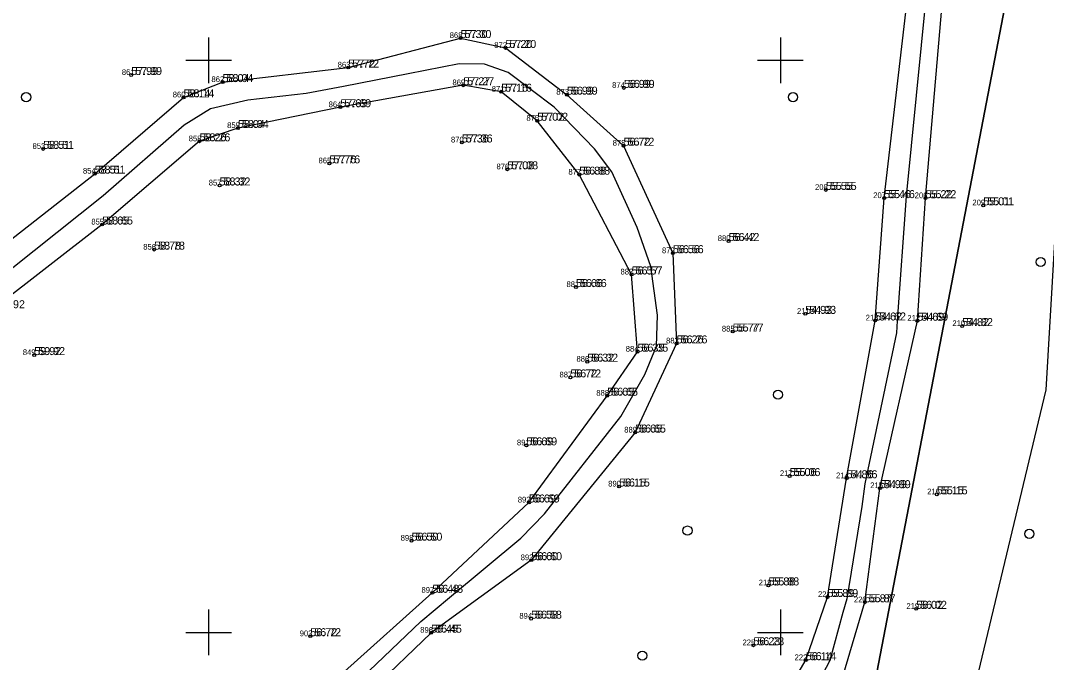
# Model space of a CAD drawing. Extents: x 554846 to 556995, y 6445875 to 6446723.
# Drawn here: x 555383.6 to 555473.3, y 6446097.4 to 6446153.5 of the extents above; entities that cross this region are included whole.
import ezdxf

# ---------------------------------------------------------------- set-up
doc = ezdxf.new("R2010")
doc.units = 0
for name, color, linetype in [('HALJASTUS', 7, 'Continuous'), ('KORGUS-EH2000', 7, 'Continuous'), ('MOOTKORG-EH2000', 7, 'Continuous'), ('MOOTMPUNKT', 7, 'Continuous'), ('MOOTNR', 7, 'Continuous'), ('MOOTPIIR', 7, 'Continuous'), ('PIIR', 7, 'Continuous'), ('TEE', 7, 'Continuous'), ('VORK', 7, 'Continuous')]:
    doc.layers.add(name, color=color, linetype=linetype)

msp = doc.modelspace()

# ---------------------------------------------------------------- linework, layer by layer
at = {"layer": 'HALJASTUS'}
for centre in [(555384.049, 6446146.781), (555451.109, 6446146.781), (555472.76, 6446132.363), (555449.791, 6446120.771), (555441.879, 6446108.897), (555471.771, 6446108.615), (555437.923, 6446097.966)]:
    msp.add_circle(centre, 0.4, dxfattribs=at)
at = {"layer": 'KORGUS-EH2000'}
for centre in [(555422.033, 6446151.944), (555425.956, 6446151.079), (555412.213, 6446149.366), (555393.235, 6446148.715), (555401.222, 6446148.095), (555422.273, 6446147.818), (555436.31, 6446147.587), (555397.814, 6446146.759), (555425.583, 6446147.254), (555431.331, 6446146.995), (555411.521, 6446145.9), (555402.569, 6446144.081), (555428.739, 6446144.714), (555385.532, 6446142.255), (555399.209, 6446142.919), (555422.143, 6446142.817), (555436.284, 6446142.533), (555410.559, 6446140.992), (555426.122, 6446140.471), (555390.037, 6446140.091), (555432.413, 6446140.005), (555400.96, 6446139.057), (555453.976, 6446138.669), (555459.068, 6446137.953), (555462.692, 6446137.947), (555467.738, 6446137.321), (555390.695, 6446135.647), (555445.472, 6446134.202), (555395.237, 6446133.451), (555440.596, 6446133.14), (555436.993, 6446131.28), (555432.12, 6446130.179), (555452.177, 6446127.836), (555458.286, 6446127.259), (555461.978, 6446127.235), (555445.832, 6446126.292), (555465.891, 6446126.77), (555440.927, 6446125.255), (555384.754, 6446124.235), (555437.502, 6446124.533), (555433.115, 6446123.656), (555431.632, 6446122.282), (555434.853, 6446120.682), (555437.295, 6446117.463), (555427.784, 6446116.344), (555450.807, 6446113.66), (555455.792, 6446113.469), (555435.891, 6446112.746), (555458.705, 6446112.603), (555463.681, 6446112.063), (555428.011, 6446111.351), (555417.745, 6446108.013), (555428.215, 6446106.306), (555448.952, 6446104.102), (555419.563, 6446103.459), (555454.113, 6446103.09), (555457.379, 6446102.627), (555461.87, 6446102.056), (555428.198, 6446101.197), (555419.454, 6446099.97), (555408.89, 6446099.662), (555447.636, 6446098.872), (555452.214, 6446097.567)]:
    msp.add_circle(centre, 0.125, dxfattribs=at)
at = {"layer": 'MOOTMPUNKT'}
for centre in [(555422.033, 6446151.944), (555425.956, 6446151.079), (555412.213, 6446149.366), (555393.235, 6446148.715), (555401.222, 6446148.095), (555422.273, 6446147.818), (555436.31, 6446147.587), (555397.814, 6446146.759), (555425.583, 6446147.254), (555431.331, 6446146.995), (555411.521, 6446145.9), (555402.569, 6446144.081), (555428.739, 6446144.714), (555385.532, 6446142.255), (555399.209, 6446142.919), (555422.143, 6446142.817), (555436.284, 6446142.533), (555410.559, 6446140.992), (555426.122, 6446140.471), (555390.037, 6446140.091), (555432.413, 6446140.005), (555400.96, 6446139.057), (555453.976, 6446138.669), (555459.068, 6446137.953), (555462.692, 6446137.947), (555467.738, 6446137.321), (555390.695, 6446135.647), (555445.472, 6446134.202), (555395.237, 6446133.451), (555440.596, 6446133.14), (555436.993, 6446131.28), (555432.12, 6446130.179), (555452.177, 6446127.836), (555458.286, 6446127.259), (555461.978, 6446127.235), (555445.832, 6446126.292), (555465.891, 6446126.77), (555440.927, 6446125.255), (555384.754, 6446124.235), (555437.502, 6446124.533), (555433.115, 6446123.656), (555431.632, 6446122.282), (555434.853, 6446120.682), (555437.295, 6446117.463), (555427.784, 6446116.344), (555450.807, 6446113.66), (555455.792, 6446113.469), (555435.891, 6446112.746), (555458.705, 6446112.603), (555463.681, 6446112.063), (555428.011, 6446111.351), (555417.745, 6446108.013), (555428.215, 6446106.306), (555448.952, 6446104.102), (555419.563, 6446103.459), (555454.113, 6446103.09), (555457.379, 6446102.627), (555461.87, 6446102.056), (555428.198, 6446101.197), (555419.454, 6446099.97), (555408.89, 6446099.662), (555447.636, 6446098.872), (555452.214, 6446097.567)]:
    msp.add_circle(centre, 0.125, dxfattribs=at)
at = {"layer": 'MOOTPIIR'}
msp.add_lwpolyline([(555856.555, 6446356.048), (555752.836, 6446263.064), (555653.542, 6446239.265), (555594.535, 6446196.056), (555554.977, 6446185.172), (555476.191, 6446171.978), (555473.224, 6446121.184), (555464.983, 6446086.881), (555439.929, 6446060.824), (555399.382, 6446041.363), (555318.618, 6446036.416), (555233.239, 6446050.269)], dxfattribs=at)
at = {"layer": 'PIIR'}
msp.add_lwpolyline([(555848.15, 6446270.05), (555770.44, 6446257.1), (555601.76, 6446236.19), (555592.08, 6446205.8), (555590.17, 6446199.81), (555547.72, 6446198.88), (555471.93, 6446166.68), (555437.75, 6445988.89), (555430.84, 6445989.84), (555424.9, 6445990.66), (555394.94, 6445995.15), (555348.46, 6446002.11), (555303.97, 6446008.78), (555290.27, 6445950.91), (555289.66, 6445948.39), (555259.76, 6445985.47)], dxfattribs=at)
msp.add_lwpolyline([(555594.35, 6446199.31), (555580.72, 6446194.53), (555573.2, 6446192.45), (555562.73, 6446139.8), (555499.33, 6446154.09), (555491.55, 6446119.62), (555486.57, 6446097.52), (555481.82, 6446076.44), (555475.25, 6446047.27), (555464.73, 6446000.58), (555471.74, 6445999.08), (555467.38, 6445984.82), (555437.75, 6445988.89), (555471.93, 6446166.68), (555547.72, 6446198.88), (555590.17, 6446199.81)], close=True, dxfattribs=at)
at = {"layer": 'TEE'}
for points in [[(555455.467, 6446096.135), (555457.379, 6446102.627), (555458.705, 6446112.603), (555461.978, 6446127.235), (555462.692, 6446137.947), (555464.165, 6446155.222), (555464.888, 6446168.091), (555460.718, 6446178.087), (555458.182, 6446181.43), (555454.567, 6446187.282), (555447.334, 6446193.455), (555438.945, 6446198.778), (555431.081, 6446205.966), (555443.842, 6446207.197), (555455.762, 6446204.58), (555468.833, 6446198.189), (555475.066, 6446194.836)], [(555449.194, 6446092.47), (555452.214, 6446097.567), (555454.113, 6446103.09), (555455.792, 6446113.469), (555458.286, 6446127.259), (555459.068, 6446137.953), (555461.161, 6446155.974), (555461.088, 6446167.397), (555455.935, 6446177.178), (555454.036, 6446179.674), (555450.224, 6446185.653), (555445.278, 6446190.027), (555436.561, 6446196.434), (555428.776, 6446203.669), (555411.969, 6446206.659), (555401.236, 6446203.893), (555388.023, 6446199.971), (555376.051, 6446196.325)], [(555462.761, 6446155.758), (555461.011, 6446138.135), (555460.216, 6446127.225), (555460.14, 6446126.188), (555457.395, 6446112.968), (555457.12, 6446110.989), (555455.797, 6446102.941), (555455.466, 6446101.723), (555454.331, 6446097.543), (555453.685, 6446096.323)], [(555330.138, 6446095.193), (555336.092, 6446099.058), (555343.079, 6446106.38), (555345.217, 6446109.048), (555355.929, 6446113.292), (555363.874, 6446119.42), (555374.157, 6446127.256), (555379.516, 6446131.875), (555390.037, 6446140.091), (555397.814, 6446146.759), (555401.222, 6446148.095), (555412.213, 6446149.366), (555422.033, 6446151.944), (555425.956, 6446151.079), (555431.331, 6446146.995), (555436.284, 6446142.533), (555440.596, 6446133.14), (555440.927, 6446125.255), (555437.295, 6446117.463), (555428.215, 6446106.306), (555419.454, 6446099.97), (555414.313, 6446095.012)], [(555413.39, 6446096.014), (555418.564, 6446100.937), (555421.075, 6446103.036), (555427.3, 6446108.241), (555429.382, 6446110.355), (555436.044, 6446118.871), (555438.142, 6446122.527), (555439.155, 6446125.025), (555439.244, 6446127.719), (555438.673, 6446131.988), (555437.48, 6446135.391), (555435.273, 6446140.241), (555433.753, 6446142.269), (555430.226, 6446145.893), (555426.19, 6446148.941), (555424.112, 6446149.657), (555421.914, 6446149.692), (555417.455, 6446148.825), (555411.786, 6446147.723), (555408.518, 6446147.087), (555403.418, 6446146.508), (555400.167, 6446145.764), (555397.852, 6446144.336), (555390.782, 6446138.154), (555380.688, 6446130.154)], [(555411.889, 6446096.584), (555419.563, 6446103.459), (555428.011, 6446111.351), (555434.853, 6446120.682), (555437.502, 6446124.533), (555436.993, 6446131.28), (555432.413, 6446140.005), (555428.739, 6446144.714), (555425.583, 6446147.254), (555422.273, 6446147.818), (555411.521, 6446145.9), (555402.569, 6446144.081), (555399.209, 6446142.919), (555390.695, 6446135.647), (555381.245, 6446128.33), (555374.773, 6446123.196), (555366.199, 6446116.974), (555358.225, 6446110.676), (555348.051, 6446105.874), (555346.97, 6446105.409), (555344.88, 6446103.864), (555338.651, 6446097.801), (555331.388, 6446092.027)]]:
    msp.add_lwpolyline(points, dxfattribs=at)
at = {"layer": 'VORK'}
for p, q in [((555400, 6446152), (555400, 6446148)), ((555450, 6446152), (555450, 6446148)), ((555398, 6446150), (555402, 6446150)), ((555448, 6446150), (555452, 6446150)), ((555400, 6446102), (555400, 6446098)), ((555450, 6446102), (555450, 6446098)), ((555398, 6446100), (555402, 6446100)), ((555448, 6446100), (555452, 6446100))]:
    msp.add_line(p, q, dxfattribs=at)

# ---------------------------------------------------------------- texts
at = {"layer": 'KORGUS-EH2000'}
for s, p in [('57.30', (555422.383, 6446151.944)), ('57.20', (555426.306, 6446151.079)), ('57.99', (555393.585, 6446148.715)), ('57.72', (555412.563, 6446149.366)), ('58.04', (555401.572, 6446148.095)), ('57.27', (555422.623, 6446147.818)), ('57.16', (555425.933, 6446147.254)), ('56.99', (555431.681, 6446146.995)), ('56.99', (555436.66, 6446147.587)), ('58.14', (555398.164, 6446146.759)), ('57.69', (555411.871, 6446145.9)), ('57.02', (555429.089, 6446144.714)), ('58.04', (555402.919, 6446144.081)), ('58.26', (555399.559, 6446142.919)), ('57.36', (555422.493, 6446142.817)), ('56.72', (555436.634, 6446142.533)), ('58.51', (555385.882, 6446142.255)), ('57.76', (555410.909, 6446140.992)), ('58.51', (555390.387, 6446140.091)), ('57.08', (555426.472, 6446140.471)), ('56.88', (555432.763, 6446140.005)), ('58.32', (555401.31, 6446139.057)), ('55.55', (555454.326, 6446138.669)), ('55.46', (555459.418, 6446137.953)), ('55.22', (555463.042, 6446137.947)), ('55.01', (555468.088, 6446137.321)), ('58.65', (555391.045, 6446135.647)), ('58.78', (555395.587, 6446133.451)), ('56.42', (555445.822, 6446134.202)), ('56.56', (555440.946, 6446133.14)), ('56.57', (555437.343, 6446131.28)), ('56.66', (555432.47, 6446130.179)), ('59.92', (555381.595, 6446128.33)), ('54.93', (555452.527, 6446127.836)), ('54.62', (555458.636, 6446127.259)), ('54.69', (555462.328, 6446127.235)), ('55.77', (555446.182, 6446126.292)), ('54.82', (555466.241, 6446126.77)), ('56.35', (555437.852, 6446124.533)), ('56.26', (555441.277, 6446125.255)), ('59.92', (555385.104, 6446124.235)), ('56.32', (555433.465, 6446123.656)), ('56.72', (555431.982, 6446122.282)), ('56.65', (555435.203, 6446120.682)), ('56.65', (555437.645, 6446117.463)), ('56.69', (555428.134, 6446116.344)), ('55.06', (555451.157, 6446113.66)), ('54.86', (555456.142, 6446113.469)), ('56.15', (555436.241, 6446112.746)), ('54.99', (555459.055, 6446112.603)), ('55.15', (555464.031, 6446112.063)), ('56.69', (555428.361, 6446111.351)), ('56.50', (555418.095, 6446108.013)), ('56.60', (555428.565, 6446106.306)), ('55.88', (555449.302, 6446104.102)), ('56.48', (555419.913, 6446103.459)), ('55.89', (555454.463, 6446103.09)), ('55.87', (555457.729, 6446102.627)), ('56.02', (555462.22, 6446102.056)), ('56.58', (555428.548, 6446101.197)), ('56.72', (555409.24, 6446099.662)), ('56.45', (555419.804, 6446099.97)), ('56.23', (555447.986, 6446098.872)), ('56.14', (555452.564, 6446097.567))]:
    msp.add_text(s, height=0.7, dxfattribs=at).set_placement(p)
at = {"layer": 'MOOTKORG-EH2000'}
for s, p in [('57.30', (555422.033, 6446151.944)), ('57.20', (555425.956, 6446151.079)), ('57.99', (555393.235, 6446148.715)), ('57.72', (555412.213, 6446149.366)), ('58.04', (555401.222, 6446148.095)), ('57.27', (555422.273, 6446147.818)), ('57.16', (555425.583, 6446147.254)), ('56.99', (555431.331, 6446146.995)), ('56.99', (555436.31, 6446147.587)), ('58.14', (555397.814, 6446146.759)), ('57.69', (555411.521, 6446145.9)), ('57.02', (555428.739, 6446144.714)), ('58.04', (555402.569, 6446144.081)), ('58.26', (555399.209, 6446142.919)), ('57.36', (555422.143, 6446142.817)), ('56.72', (555436.284, 6446142.533)), ('58.51', (555385.532, 6446142.255)), ('57.76', (555410.559, 6446140.992)), ('58.51', (555390.037, 6446140.091)), ('57.08', (555426.122, 6446140.471)), ('56.88', (555432.413, 6446140.005)), ('58.32', (555400.96, 6446139.057)), ('55.55', (555453.976, 6446138.669)), ('55.46', (555459.068, 6446137.953)), ('55.22', (555462.692, 6446137.947)), ('55.01', (555467.738, 6446137.321)), ('58.65', (555390.695, 6446135.647)), ('58.78', (555395.237, 6446133.451)), ('56.42', (555445.472, 6446134.202)), ('56.56', (555440.596, 6446133.14)), ('56.57', (555436.993, 6446131.28)), ('56.66', (555432.12, 6446130.179)), ('54.93', (555452.177, 6446127.836)), ('54.62', (555458.286, 6446127.259)), ('54.69', (555461.978, 6446127.235)), ('55.77', (555445.832, 6446126.292)), ('54.82', (555465.891, 6446126.77)), ('56.35', (555437.502, 6446124.533)), ('56.26', (555440.927, 6446125.255)), ('59.92', (555384.754, 6446124.235)), ('56.32', (555433.115, 6446123.656)), ('56.72', (555431.632, 6446122.282)), ('56.65', (555434.853, 6446120.682)), ('56.65', (555437.295, 6446117.463)), ('56.69', (555427.784, 6446116.344)), ('55.06', (555450.807, 6446113.66)), ('54.86', (555455.792, 6446113.469)), ('56.15', (555435.891, 6446112.746)), ('54.99', (555458.705, 6446112.603)), ('55.15', (555463.681, 6446112.063)), ('56.69', (555428.011, 6446111.351)), ('56.50', (555417.745, 6446108.013)), ('56.60', (555428.215, 6446106.306)), ('55.88', (555448.952, 6446104.102)), ('56.48', (555419.563, 6446103.459)), ('55.89', (555454.113, 6446103.09)), ('55.87', (555457.379, 6446102.627)), ('56.02', (555461.87, 6446102.056)), ('56.58', (555428.198, 6446101.197)), ('56.72', (555408.89, 6446099.662)), ('56.45', (555419.454, 6446099.97)), ('56.23', (555447.636, 6446098.872)), ('56.14', (555452.214, 6446097.567))]:
    msp.add_text(s, height=0.7, dxfattribs=at).set_placement(p)
at = {"layer": 'MOOTNR'}
for s, p in [('868', (555421.083, 6446151.944)), ('872', (555424.981, 6446151.079)), ('863', (555411.288, 6446149.366)), ('861', (555392.41, 6446148.715)), ('862', (555400.247, 6446148.095)), ('869', (555421.323, 6446147.818)), ('871', (555424.758, 6446147.254)), ('874', (555435.285, 6446147.587)), ('860', (555396.864, 6446146.759)), ('873', (555430.406, 6446146.995)), ('864', (555410.496, 6446145.9)), ('875', (555427.789, 6446144.714)), ('859', (555401.619, 6446144.081)), ('858', (555398.259, 6446142.919)), ('870', (555421.193, 6446142.817)), ('853', (555384.607, 6446142.255)), ('878', (555435.334, 6446142.533)), ('865', (555409.609, 6446140.992)), ('854', (555389.012, 6446140.091)), ('876', (555425.172, 6446140.471)), ('877', (555431.463, 6446140.005)), ('857', (555400.01, 6446139.057)), ('208', (555453.026, 6446138.669)), ('207', (555458.118, 6446137.953)), ('206', (555461.742, 6446137.947)), ('209', (555466.788, 6446137.321)), ('855', (555389.745, 6446135.647)), ('880', (555444.522, 6446134.202)), ('856', (555394.287, 6446133.451)), ('879', (555439.646, 6446133.14)), ('882', (555436.018, 6446131.28)), ('881', (555431.295, 6446130.179)), ('211', (555451.452, 6446127.836)), ('213', (555457.461, 6446127.259)), ('212', (555461.103, 6446127.235)), ('210', (555465.041, 6446126.77)), ('885', (555444.882, 6446126.292)), ('883', (555440.002, 6446125.255)), ('849', (555383.754, 6446124.235)), ('884', (555436.477, 6446124.533)), ('886', (555432.165, 6446123.656)), ('887', (555430.682, 6446122.282)), ('888', (555433.903, 6446120.682)), ('889', (555436.345, 6446117.463)), ('891', (555426.959, 6446116.344)), ('217', (555449.957, 6446113.66)), ('214', (555454.867, 6446113.469)), ('890', (555434.941, 6446112.746)), ('215', (555457.855, 6446112.603)), ('892', (555427.036, 6446111.351)), ('216', (555462.831, 6446112.063)), ('898', (555416.795, 6446108.013)), ('893', (555427.29, 6446106.306)), ('218', (555448.102, 6446104.102)), ('897', (555418.613, 6446103.459)), ('221', (555453.288, 6446103.09)), ('220', (555456.429, 6446102.627)), ('219', (555461.02, 6446102.056)), ('894', (555427.173, 6446101.197)), ('903', (555407.965, 6446099.662)), ('896', (555418.504, 6446099.97)), ('225', (555446.686, 6446098.872)), ('222', (555451.239, 6446097.567))]:
    msp.add_text(s, height=0.5, dxfattribs=at).set_placement(p)

doc.saveas('drawing.dxf')
